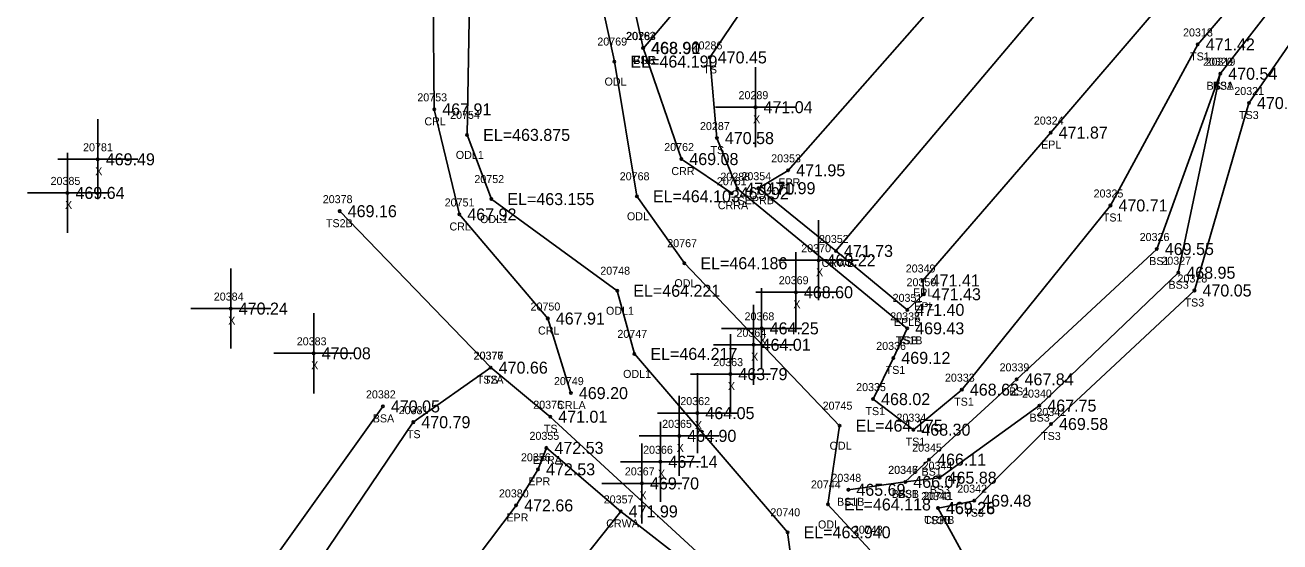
# Model space of a CAD drawing. Extents: x 1741010 to 1742139, y 749382 to 750625.
# Drawn here: x 1741509 to 1741665.8, y 750041.3 to 750105.8 of the extents above; entities that cross this region are included whole.
import ezdxf

# ---------------------------------------------------------------- set-up
doc = ezdxf.new("R2010")
doc.units = 0
for name, color, linetype in [('RD_DTM_BkLn1', 7, 'Continuous'), ('RD_DTM_BkLn2', 7, 'Continuous'), ('RD_DTM_BkLn_txCode', 7, 'Continuous'), ('RD_EX_H2O', 7, 'Continuous'), ('RD_EX_H2O_txCode', 7, 'Continuous'), ('RD_EX_Misc', 7, 'Continuous'), ('RD_EX_Misc_txCode', 7, 'Continuous'), ('RD_EX_Road', 7, 'Continuous'), ('RD_EX_Road_txCode', 7, 'Continuous'), ('RD_EX_TX_H2O_ELEV', 7, 'Continuous'), ('RD_EX_TX_Misc_ELEV', 7, 'Continuous'), ('RD_EX_TX_Road_ELEV', 7, 'Continuous'), ('RD_HC_Survey_ELEV', 7, 'Continuous'), ('RD_HC_Survey_txCode', 7, 'Continuous'), ('RD_SMD_Locator', 7, 'Continuous')]:
    doc.layers.add(name, color=color, linetype=linetype)

msp = doc.modelspace()

# ---------------------------------------------------------------- linework, layer by layer
at = {"layer": 'RD_DTM_BkLn1'}
for points in [[(1742095.1, 750579.47), (1742056.96, 750547.11), (1742019.74, 750514.22), (1741983.45, 750480.17), (1741948.01, 750445.01), (1741913.15, 750409.3), (1741879.03, 750372.99), (1741811.59, 750300.09), (1741743.65, 750226.52), (1741676.29, 750153.06), (1741642.32, 750115.53), (1741610.32, 750077.63)], [(1741583.42, 750045.09), (1741578.78, 750039.19), (1741548.6, 749999.46), (1741519.68, 749959.35), (1741491.7, 749918.15), (1741464.01, 749876.67), (1741436.51, 749835.23), (1741409.05, 749793.46), (1741381.95, 749752.07), (1741327.4, 749668.12), (1741273.18, 749584.75), (1741218.51, 749501.3), (1741163.8, 749416.96)]]:
    msp.add_lwpolyline(points, dxfattribs=at)
at = {"layer": 'RD_DTM_BkLn2'}
msp.add_line((1741567.17, 750063.05), (1741548.3, 750082.6), dxfattribs=at)
for points in [[(1742105.6, 750567.48), (1742094.25, 750560.49), (1742091.64, 750555.7), (1742067.93, 750534.94), (1742031.73, 750501.95), (1741994.85, 750467.63), (1741959.82, 750432.06), (1741925.8, 750396.31), (1741891.25, 750362.62), (1741824.36, 750287.7), (1741756.44, 750214.6), (1741688.69, 750142.04), (1741655.55, 750103.43), (1741644.64, 750083.31), (1741626.06, 750060.3), (1741620, 750055.3), (1741614.97, 750059.12), (1741617.5, 750064.27), (1741619.23, 750067.96)], [(1742107.37, 750564.98), (1742099.21, 750558.66), (1742095.99, 750559.5), (1742095.15, 750554.39), (1742069.73, 750532.61), (1742034.06, 750499.81), (1741997.6, 750464.99), (1741961.88, 750429.54), (1741928.13, 750394.17), (1741895.34, 750359.02), (1741826.5, 750286.36), (1741758.73, 750213.29), (1741690.1, 750140.59), (1741658.36, 750099.77), (1741650.43, 750077.87), (1741632.9, 750061.59), (1741621.97, 750051.56), (1741618.99, 750048.78), (1741611.88, 750047.79)], [(1742108.6, 750563.87), (1742101.48, 750556.48), (1742102.57, 750548.5), (1742101.05, 750532.99), (1742105.06, 750513.92), (1742103.27, 750510.53), (1742100.54, 750509.6), (1742099.13, 750514.58), (1742095.78, 750530.6), (1742094.19, 750550.08), (1742071, 750531.59), (1742035.26, 750498.87), (1741998.91, 750463.73), (1741964.71, 750427.12), (1741930.26, 750392.09), (1741896.36, 750357.96), (1741828.15, 750284.74), (1741760.22, 750211.9), (1741691.37, 750138.81), (1741661.95, 750096.11), (1741655.14, 750072.69), (1741637.21, 750056.01), (1741627.61, 750046.43), (1741623.09, 750045.5)], [(1741687.02, 750214.18), (1741699.03, 750211.31), (1741701.37, 750206.33), (1741693.87, 750197.73), (1741661.42, 750168.06), (1741625.78, 750132.25), (1741598.95, 750108.26), (1741594.55, 750101.81), (1741595.44, 750091.73), (1741598, 750085.41), (1741619.23, 750067.96)], [(1741697.46, 750209.37), (1741696.69, 750207.39), (1741687.32, 750198.15), (1741655.45, 750172.38), (1741616.11, 750137.65), (1741593.67, 750111.75), (1741586.25, 750102.97)], [(1741658.36, 750099.77), (1741653.12, 750074.91), (1741635.75, 750058.31), (1741623.28, 750049.3), (1741618.99, 750048.78)], [(1741619.24, 750070.27), (1741610.32, 750077.63), (1741600.63, 750085.47)], [(1741595, 750038.14), (1741574.61, 750056.92), (1741567.17, 750063.05), (1741557.5, 750056.24), (1741528.84, 750013.89), (1741502.42, 749971.51), (1741486.02, 749940.89), (1741477.71, 749927.84), (1741450.78, 749885.21), (1741423.85, 749843.58), (1741396.77, 749800.81), (1741369.66, 749759.51), (1741314.64, 749675.74), (1741265.52, 749598.52), (1741262.68, 749595.73), (1741260.89, 749596.52)], [(1741553.69, 750058.21), (1741524.69, 750017.65), (1741497.38, 749974.6), (1741482.49, 749941.95), (1741475.22, 749929.78), (1741449.41, 749886.55), (1741422.56, 749844.68), (1741395.22, 749801.69), (1741368.2, 749760.22), (1741313.51, 749676.19), (1741261.6, 749597.61)], [(1741592.65, 750037.91), (1741583.42, 750045.09), (1741574.14, 750053.03)]]:
    msp.add_lwpolyline(points, dxfattribs=at)
at = {"layer": 'RD_EX_H2O'}
for points in [[(1741577.19, 750059.87), (1741574.31, 750069.19), (1741563.25, 750082.19), (1741560.12, 750095.32), (1741559.96, 750109.5), (1741556.5, 750127.16), (1741554.14, 750131.7), (1741543.79, 750140.45), (1741537.22, 750131.72), (1741525.85, 750130.27), (1741518.7, 750134.1), (1741490.89, 750135.06), (1741436.94, 750142.19), (1741375.71, 750163.12), (1741339.37, 750188.79), (1741331.64, 750190.2), (1741328.64, 750186.11), (1741320.24, 750158.32), (1741318.27, 750146.83), (1741309.48, 750135.97), (1741304.66, 750127.91)], [(1741614.56, 750040.31), (1741609.32, 750045.96), (1741610.78, 750055.8), (1741591.38, 750076.1), (1741585.44, 750084.46), (1741582.64, 750101.29), (1741578.14, 750121.91), (1741571.53, 750133.18), (1741571.15, 750156.02), (1741553.39, 750165.18), (1741547.39, 750158.73), (1741529.44, 750151.69), (1741495.88, 750157.28)], [(1741605.22, 750035.39), (1741604.28, 750042.48), (1741585.13, 750064.77), (1741582.99, 750072.66), (1741567.25, 750084.11), (1741564.22, 750092.13), (1741564.57, 750111.37), (1741564.38, 750132.49), (1741555.63, 750132.44), (1741544.08, 750143.37), (1741535.8, 750134.85), (1741528.08, 750133.48), (1741521.3, 750138.92), (1741491.52, 750137.44)], [(1741597.3, 750084.84), (1741591, 750089.11), (1741586.21, 750103), (1741580.45, 750128.97), (1741581.18, 750134.22), (1741591.16, 750136.52)], [(1742009.73, 749699.92), (1741998.41, 749723.73), (1741963.19, 749743.52), (1741899.78, 749744.87), (1741875.61, 749759.72), (1741846.8, 749796.06), (1741820.86, 749838.72), (1741812.23, 749854.24), (1741798.02, 749868.34), (1741757.86, 749894.19), (1741733.12, 749942.57), (1741724.29, 749959.1), (1741692.79, 749978.15), (1741670.02, 749986.94), (1741660.12, 749986.72), (1741653.47, 749993.98), (1741643.26, 750008.63), (1741623.07, 750045.53)]]:
    msp.add_lwpolyline(points, dxfattribs=at)
at = {"layer": 'RD_EX_Misc'}
for p, q in [((1741600.27, 750090.59), (1741600.27, 750100.59)), ((1741595.27, 750095.59), (1741605.27, 750095.59)), ((1741518.06, 750084.08), (1741518.06, 750094.08)), ((1741514.27, 750079.88), (1741514.27, 750089.88)), ((1741513.06, 750089.08), (1741523.06, 750089.08)), ((1741509.27, 750084.88), (1741519.27, 750084.88)), ((1741608.15, 750071.47), (1741608.15, 750081.47)), ((1741605.32, 750067.47), (1741605.32, 750077.47)), ((1741534.68, 750065.43), (1741534.68, 750075.43)), ((1741603.15, 750076.47), (1741613.15, 750076.47)), ((1741600.32, 750072.47), (1741610.32, 750072.47)), ((1741601.04, 750062.96), (1741601.04, 750072.96)), ((1741600.03, 750060.91), (1741600.03, 750070.91)), ((1741529.68, 750070.43), (1741539.68, 750070.43)), ((1741545.05, 750059.84), (1741545.05, 750069.84)), ((1741596.04, 750067.96), (1741606.04, 750067.96)), ((1741595.03, 750065.91), (1741605.03, 750065.91)), ((1741597.13, 750057.24), (1741597.13, 750067.24)), ((1741540.05, 750064.84), (1741550.05, 750064.84)), ((1741592.13, 750062.24), (1741602.13, 750062.24)), ((1741593.01, 750052.37), (1741593.01, 750062.37)), ((1741590.74, 750049.53), (1741590.74, 750059.53)), ((1741588.01, 750057.37), (1741598.01, 750057.37)), ((1741588.39, 750046.29), (1741588.39, 750056.29)), ((1741585.74, 750054.53), (1741595.74, 750054.53)), ((1741586.08, 750043.59), (1741586.08, 750053.59)), ((1741583.39, 750051.29), (1741593.39, 750051.29)), ((1741581.08, 750048.59), (1741591.08, 750048.59))]:
    msp.add_line(p, q, dxfattribs=at)
at = {"layer": 'RD_EX_Road'}
for points in [[(1742095.24, 750593.27), (1742088.27, 750587.97), (1742078.23, 750580.89), (1742049.13, 750555.21), (1742012.94, 750522.73), (1741975.54, 750488.03), (1741940.71, 750452.82), (1741916.22, 750428.67), (1741904.72, 750416.99), (1741884.38, 750395.02), (1741870.75, 750380.27), (1741817.36, 750322.98), (1741803.89, 750307.66), (1741783.86, 750287.33), (1741735.44, 750234.07), (1741718.84, 750214.98), (1741710.25, 750205.58), (1741668.97, 750159.8), (1741635, 750122.49), (1741604.35, 750087.7), (1741600.63, 750085.47)], [(1742102.43, 750570.61), (1742093.26, 750562.71), (1742064.72, 750538.42), (1742027.92, 750505.65), (1741991.25, 750471.83), (1741956.32, 750436.98), (1741921.43, 750401.39), (1741886.79, 750364.93), (1741819.64, 750292.67), (1741751.78, 750219.01), (1741684.42, 750145.59), (1741650.98, 750108.5), (1741637.17, 750092.42), (1741621.17, 750073.94), (1741621.31, 750072.22), (1741619.24, 750070.27)], [(1741574.14, 750053.03), (1741573.09, 750050.35), (1741570.35, 750045.84), (1741539.87, 750005.43), (1741510.87, 749966.19), (1741482.97, 749924.75), (1741454.76, 749883.01), (1741427.14, 749841.37), (1741399.6, 749799.14), (1741372.83, 749758.13), (1741317.93, 749673.6), (1741267.39, 749595.97), (1741263.6, 749591.05), (1741254, 749576.22), (1741209.28, 749507.22), (1741154.74, 749422.71)]]:
    msp.add_lwpolyline(points, dxfattribs=at)
at = {"layer": 'RD_SMD_Locator'}
for centre in [(1741655.55, 750103.43), (1741586.21, 750103), (1741586.25, 750102.97), (1741594.55, 750101.81), (1741582.64, 750101.29), (1741658.36, 750099.77), (1741658.36, 750099.77), (1741600.27, 750095.59), (1741661.95, 750096.11), (1741560.12, 750095.32), (1741637.17, 750092.42), (1741564.22, 750092.13), (1741595.44, 750091.73), (1741518.06, 750089.08), (1741591, 750089.11), (1741604.35, 750087.7), (1741514.27, 750084.88), (1741597.3, 750084.84), (1741598, 750085.41), (1741600.63, 750085.47), (1741567.25, 750084.11), (1741585.44, 750084.46), (1741644.64, 750083.31), (1741548.3, 750082.6), (1741563.25, 750082.19), (1741610.32, 750077.63), (1741650.43, 750077.87), (1741591.38, 750076.1), (1741608.15, 750076.47), (1741621.17, 750073.94), (1741653.12, 750074.91), (1741582.99, 750072.66), (1741605.32, 750072.47), (1741621.31, 750072.22), (1741655.14, 750072.69), (1741534.68, 750070.43), (1741574.31, 750069.19), (1741619.24, 750070.27), (1741601.04, 750067.96), (1741619.23, 750067.96), (1741619.23, 750067.96), (1741600.03, 750065.91), (1741545.05, 750064.84), (1741585.13, 750064.77), (1741617.5, 750064.27), (1741567.17, 750063.05), (1741567.17, 750063.05), (1741597.13, 750062.24), (1741632.9, 750061.59), (1741577.19, 750059.87), (1741626.06, 750060.3), (1741553.69, 750058.21), (1741614.97, 750059.12), (1741635.75, 750058.31), (1741574.61, 750056.92), (1741593.01, 750057.37), (1741557.5, 750056.24), (1741610.78, 750055.8), (1741620, 750055.3), (1741637.21, 750056.01), (1741590.74, 750054.53), (1741574.14, 750053.03), (1741573.09, 750050.35), (1741588.39, 750051.29), (1741621.97, 750051.56), (1741586.08, 750048.59), (1741618.99, 750048.78), (1741618.99, 750048.78), (1741623.28, 750049.3), (1741611.88, 750047.79), (1741570.35, 750045.84), (1741609.32, 750045.96), (1741623.07, 750045.53), (1741623.09, 750045.5), (1741627.61, 750046.43), (1741583.42, 750045.09), (1741604.28, 750042.48)]:
    msp.add_circle(centre, 0.15, dxfattribs=at)

# ---------------------------------------------------------------- texts
at = {"layer": 'RD_DTM_BkLn_txCode'}
for s, p in [('20318', (1741653.71, 750104.43)), ('20284', (1741584.13, 750103.97)), ('20286', (1741592.41, 750102.81)), ('BSB', (1741584.99, 750100.97)), ('TS1', (1741654.59, 750101.43)), ('TS', (1741593.75, 750099.81)), ('20320', (1741656.21, 750100.77)), ('20319', (1741656.53, 750100.77)), ('BS3A', (1741656.65, 750097.77)), ('BS1', (1741657.42, 750097.77)), ('20321', (1741660.12, 750097.11)), ('TS3', (1741660.71, 750094.11)), ('20287', (1741593.33, 750092.73)), ('TS', (1741594.65, 750089.73)), ('20288', (1741595.88, 750086.41)), ('20325', (1741642.53, 750084.31)), ('20378', (1741546.18, 750083.6)), ('TS', (1741597.21, 750083.41)), ('TS2B', (1741546.58, 750080.6)), ('TS1', (1741643.68, 750081.31)), ('20326', (1741648.29, 750078.87)), ('BS1', (1741649.48, 750075.87)), ('20327', (1741651, 750075.91)), ('BS3', (1741651.89, 750072.91)), ('20328', (1741653.02, 750073.69)), ('TS3', (1741653.9, 750070.69)), ('20337', (1741617.11, 750068.96)), ('20338', (1741617.11, 750068.96)), ('20336', (1741615.36, 750065.27)), ('TS1B', (1741617.79, 750065.96)), ('TSB', (1741617.96, 750065.96)), ('20376', (1741565.02, 750064.05)), ('20377', (1741565.05, 750064.05)), ('TS1', (1741616.54, 750062.27)), ('20339', (1741630.78, 750062.59)), ('TS2A', (1741565.43, 750061.05)), ('TS', (1741566.37, 750061.05)), ('20333', (1741623.95, 750061.3)), ('20382', (1741551.58, 750059.21)), ('20335', (1741612.85, 750060.12)), ('BS1', (1741631.95, 750059.59)), ('20340', (1741633.59, 750059.31)), ('20381', (1741555.67, 750057.24)), ('20375', (1741572.49, 750057.92)), ('TS1', (1741614.01, 750057.12)), ('TS1', (1741625.1, 750058.3)), ('20341', (1741635.38, 750057.01)), ('BSA', (1741552.43, 750056.21)), ('20334', (1741617.89, 750056.3)), ('BS3', (1741634.52, 750056.31)), ('TS', (1741556.7, 750054.24)), ('TS', (1741573.82, 750054.92)), ('TS3', (1741635.97, 750054.01)), ('TS1', (1741619.04, 750053.3)), ('20345', (1741619.85, 750052.56)), ('20346', (1741616.85, 750049.78)), ('20347', (1741616.87, 750049.78)), ('BS1', (1741621.02, 750049.56)), ('20344', (1741621.16, 750050.3)), ('20348', (1741609.76, 750048.79)), ('BS3B', (1741617.29, 750046.78)), ('BS1', (1741618.05, 750046.78)), ('20343', (1741620.97, 750046.5)), ('BS3', (1741622.05, 750047.3)), ('20342', (1741625.49, 750047.43)), ('BS1B', (1741610.46, 750045.79)), ('TS3B', (1741621.37, 750043.5)), ('TS3', (1741626.37, 750044.43))]:
    msp.add_text(s, height=1, dxfattribs=at).set_placement(p)
at = {"layer": 'RD_EX_H2O_txCode'}
for s, p in [('20769', (1741580.5, 750103.29)), ('20763', (1741584.07, 750104)), ('CRR', (1741584.96, 750101)), ('ODL', (1741581.4, 750098.29)), ('20753', (1741558, 750096.32)), ('CRL', (1741558.89, 750093.32)), ('20754', (1741562.1, 750094.13)), ('20762', (1741588.86, 750090.11)), ('ODL1', (1741562.81, 750089.13)), ('CRR', (1741589.75, 750087.11)), ('20752', (1741565.13, 750086.11)), ('20768', (1741583.3, 750086.46)), ('20761', (1741595.44, 750085.84)), ('20751', (1741561.42, 750083.19)), ('CRRA', (1741595.56, 750082.84)), ('ODL1', (1741565.84, 750081.11)), ('ODL', (1741584.2, 750081.46)), ('CRL', (1741562.02, 750080.19)), ('20767', (1741589.24, 750078.1)), ('20748', (1741580.87, 750074.66)), ('ODL', (1741590.13, 750073.1)), ('20750', (1741572.15, 750070.19)), ('ODL1', (1741581.58, 750069.66)), ('CRL', (1741573.08, 750067.19)), ('20747', (1741583.01, 750066.77)), ('ODL1', (1741583.72, 750061.77)), ('20749', (1741575.08, 750060.87)), ('CRLA', (1741575.48, 750057.87)), ('20745', (1741608.66, 750057.8)), ('ODL', (1741609.53, 750052.8)), ('20744', (1741607.2, 750047.96)), ('20741', (1741621.23, 750046.53)), ('20740', (1741602.13, 750044.48)), ('ODL', (1741608.08, 750042.96)), ('CRRB', (1741621.34, 750043.53)), ('20743', (1741612.44, 750042.31))]:
    msp.add_text(s, height=1, dxfattribs=at).set_placement(p)
at = {"layer": 'RD_EX_Misc_txCode'}
for s, p in [('20289', (1741598.15, 750096.59)), ('X', (1741599.96, 750093.59)), ('20781', (1741516.22, 750090.08)), ('X', (1741517.74, 750087.08)), ('20385', (1741512.16, 750085.88)), ('X', (1741513.96, 750082.88)), ('20370', (1741605.99, 750077.47)), ('X', (1741607.84, 750074.47)), ('20369', (1741603.18, 750073.47)), ('20384', (1741532.56, 750071.43)), ('X', (1741605, 750070.47)), ('X', (1741534.36, 750068.43)), ('20368', (1741598.9, 750068.96)), ('20364', (1741597.89, 750066.91)), ('20383', (1741542.93, 750065.84)), ('X', (1741600.73, 750065.96)), ('X', (1741599.72, 750063.91)), ('X', (1741544.73, 750062.84)), ('20363', (1741594.99, 750063.24)), ('X', (1741596.82, 750060.24)), ('20362', (1741590.87, 750058.37)), ('20365', (1741588.6, 750055.53)), ('X', (1741592.69, 750055.37)), ('X', (1741590.42, 750052.53)), ('20366', (1741586.22, 750052.29)), ('20367', (1741583.94, 750049.59)), ('X', (1741588.07, 750049.29)), ('X', (1741585.77, 750046.59))]:
    msp.add_text(s, height=1, dxfattribs=at).set_placement(p)
at = {"layer": 'RD_EX_Road_txCode'}
for s, p in [('20324', (1741635.06, 750093.42)), ('EPL', (1741635.97, 750090.42)), ('20353', (1741602.23, 750088.7)), ('20354', (1741598.51, 750086.47)), ('EPR', (1741603.12, 750085.7)), ('EPRB', (1741598.93, 750083.47)), ('20349', (1741619.05, 750074.94)), ('20350', (1741619.15, 750073.22)), ('20351', (1741617.41, 750071.27)), ('EPL', (1741619.96, 750071.94)), ('EPL', (1741620.11, 750070.22)), ('EPLB', (1741617.56, 750068.27)), ('20355', (1741572.02, 750054.03)), ('20356', (1741570.95, 750051.35)), ('EPRA', (1741572.42, 750051.03)), ('EPR', (1741571.87, 750048.35)), ('20380', (1741568.2, 750046.84)), ('EPR', (1741569.13, 750043.84))]:
    msp.add_text(s, height=1, dxfattribs=at).set_placement(p)
at = {"layer": 'RD_EX_TX_H2O_ELEV'}
for s, p in [('468.90', (1741587.21, 750102.25)), ('EL=464.199', (1741584.64, 750100.54)), ('467.91', (1741561.12, 750094.57)), ('EL=463.875', (1741566.22, 750091.38)), ('469.08', (1741592, 750088.36)), ('EL=463.155', (1741569.25, 750083.36)), ('EL=464.103', (1741587.44, 750083.71)), ('469.92', (1741598.3, 750084.09)), ('467.92', (1741564.25, 750081.44)), ('EL=464.186', (1741593.38, 750075.35)), ('EL=464.221', (1741584.99, 750071.91)), ('467.91', (1741575.31, 750068.44)), ('EL=464.217', (1741587.13, 750064.02)), ('469.20', (1741578.19, 750059.12)), ('EL=464.175', (1741612.78, 750055.05)), ('EL=464.118', (1741611.32, 750045.21)), ('469.26', (1741624.07, 750044.78)), ('EL=463.940', (1741606.28, 750041.73))]:
    msp.add_text(s, height=1.5, dxfattribs=at).set_placement(p)
at = {"layer": 'RD_EX_TX_Misc_ELEV'}
for s, p in [('468.91', (1741587.25, 750102.22)), ('471.42', (1741656.55, 750102.68)), ('470.45', (1741595.55, 750101.06)), ('470.54', (1741659.36, 750099.02)), ('470.54', (1741659.36, 750099.02)), ('471.04', (1741601.27, 750094.84)), ('470.78', (1741662.95, 750095.36)), ('470.58', (1741596.44, 750090.98)), ('469.49', (1741519.06, 750088.33)), ('469.64', (1741515.27, 750084.13)), ('470.70', (1741599, 750084.66)), ('469.16', (1741549.3, 750081.85)), ('470.71', (1741645.64, 750082.56)), ('469.55', (1741651.43, 750077.12)), ('469.22', (1741609.15, 750075.72)), ('468.95', (1741654.12, 750074.16)), ('468.60', (1741606.32, 750071.72)), ('470.05', (1741656.14, 750071.94)), ('470.24', (1741535.68, 750069.68)), ('464.25', (1741602.04, 750067.21)), ('469.43', (1741620.23, 750067.21)), ('469.43', (1741620.23, 750067.21)), ('464.01', (1741601.03, 750065.16)), ('470.08', (1741546.05, 750064.09)), ('469.12', (1741618.5, 750063.52)), ('470.66', (1741568.17, 750062.3)), ('470.66', (1741568.17, 750062.3)), ('463.79', (1741598.13, 750061.49)), ('467.84', (1741633.9, 750060.84)), ('468.02', (1741615.97, 750058.37)), ('468.62', (1741627.06, 750059.55)), ('470.05', (1741554.69, 750057.46)), ('464.05', (1741594.01, 750056.62)), ('467.75', (1741636.75, 750057.56)), ('470.79', (1741558.5, 750055.49)), ('471.01', (1741575.61, 750056.17)), ('469.58', (1741638.21, 750055.26)), ('464.90', (1741591.74, 750053.78)), ('468.30', (1741621, 750054.55)), ('467.14', (1741589.39, 750050.54)), ('466.11', (1741622.97, 750050.81)), ('469.70', (1741587.08, 750047.84)), ('466.07', (1741619.99, 750048.03)), ('466.07', (1741619.99, 750048.03)), ('465.88', (1741624.28, 750048.55)), ('465.69', (1741612.88, 750047.04)), ('469.48', (1741628.61, 750045.68)), ('469.28', (1741624.09, 750044.75))]:
    msp.add_text(s, height=1.5, dxfattribs=at).set_placement(p)
at = {"layer": 'RD_EX_TX_Road_ELEV'}
for s, p in [('471.87', (1741638.17, 750091.67)), ('471.95', (1741605.35, 750086.95)), ('471.99', (1741601.63, 750084.72)), ('471.41', (1741622.17, 750073.19)), ('471.43', (1741622.31, 750071.47)), ('471.40', (1741620.24, 750069.52)), ('472.53', (1741575.14, 750052.28)), ('472.53', (1741574.09, 750049.6)), ('472.66', (1741571.35, 750045.09))]:
    msp.add_text(s, height=1.5, dxfattribs=at).set_placement(p)
at = {"layer": 'RD_HC_Survey_ELEV'}
for s, p in [('471.73', (1741611.32, 750076.88)), ('471.99', (1741584.42, 750044.34))]:
    msp.add_text(s, height=1.5, dxfattribs=at).set_placement(p)
at = {"layer": 'RD_HC_Survey_txCode'}
for s, p in [('20352', (1741608.2, 750078.63)), ('CRWB', (1741608.53, 750075.63)), ('20357', (1741581.3, 750046.09)), ('CRWA', (1741581.61, 750043.09))]:
    msp.add_text(s, height=1, dxfattribs=at).set_placement(p)

doc.saveas('drawing.dxf')
